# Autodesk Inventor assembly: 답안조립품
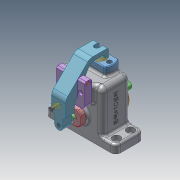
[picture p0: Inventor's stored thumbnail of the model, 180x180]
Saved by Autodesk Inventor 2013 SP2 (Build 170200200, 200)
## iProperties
Created: 2023-12
Part Number: 답안조립품
Document SubType Name: Assembly
Designer: i
Author: i
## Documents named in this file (14)
- C:\Users\i\Desktop\731208V1010\답안조립품.iam
- C:\Users\i\Desktop\731208V1010\본체.ipt
- C:\Users\i\Desktop\731208V1010\가공품.ipt
- C:\Users\i\Desktop\731208V1010\가이드 부시.ipt
- C:\Users\i\Desktop\731208V1010\고정대.ipt
- C:\Users\i\Desktop\731208V1010\브라켓.ipt
- C:\Users\i\Desktop\731208V1010\스프링.ipt
- C:\Users\i\Desktop\731208V1010\육각 머리 볼트 M6 x 12.ipt
- C:\Users\i\Desktop\731208V1010\육각 소켓 머리 볼트 M3 x 8.ipt
- C:\Users\i\Desktop\731208V1010\육각 소켓 머리 볼트 M3 x 30.ipt
- C:\Users\i\Desktop\731208V1010\조절 부시.ipt
- C:\Users\i\Desktop\731208V1010\클램프 샤프트.ipt
- C:\Users\i\Desktop\731208V1010\클램프.ipt
- C:\Users\i\Desktop\731208V1010\핀.ipt
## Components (4 placed, 4 different names)
1. 가공품:1
2. 가이드 부시:1
3. 고정대:1
4. 핀:1 — 플러쉬:1
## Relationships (1: Flush 1)
- 플러쉬:1 [Flush]: 핀:1
